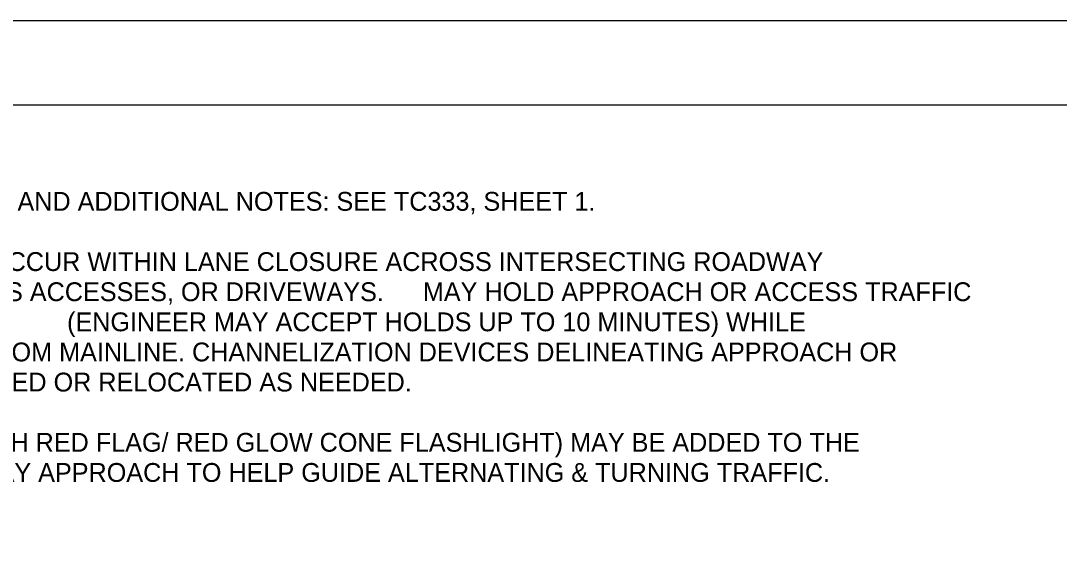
# Model space of a CAD drawing. Extents: x 99999.1 to 100095.7, y 99995 to 100010.7.
# Drawn here: x 100021.34 to 100025.2, y 100008.726 to 100010.687 of the extents above; entities that cross this region are included whole.
import ezdxf

# ---------------------------------------------------------------- set-up
doc = ezdxf.new("R2010")
doc.units = 0
for name, color, linetype in [('SH_GI_GeneralNotesBodyText', 7, 'Continuous'), ('SH_GI_PlotLimits', 7, 'Continuous'), ('SH_GI_SheetBorder', 7, 'Continuous')]:
    doc.layers.add(name, color=color, linetype=linetype)

msp = doc.modelspace()

# ---------------------------------------------------------------- linework, layer by layer
at = {"layer": 'SH_GI_PlotLimits'}
msp.add_lwpolyline([(100019.0625, 99999.6875), (100036.0625, 99999.6875), (100036.0625, 100010.6875), (100019.0625, 100010.6875)], close=True, dxfattribs=at)
at = {"layer": 'SH_GI_SheetBorder'}
msp.add_line((100020, 100010.375), (100035.75, 100010.375), dxfattribs=at)

# ---------------------------------------------------------------- texts
at = {"layer": 'SH_GI_GeneralNotesBodyText'}
for s, p in [('12. FOR LEGEND, TABLES, AND ADDITIONAL NOTES: SEE TC333, SHEET 1.', (100020.1, 100009.981)), ('13. WORK MAY BRIEFLY OCCUR WITHIN LANE CLOSURE ACROSS INTERSECTING ROADWAY ', (100020.1, 100009.757)), ('APPROACHES, BUSINESS ACCESSES, OR DRIVEWAYS. ', (100020.172, 100009.645)), ('MAY HOLD APPROACH OR ACCESS TRAFFIC ', (100022.8346, 100009.645)), (' (ENGINEER MAY ACCEPT HOLDS UP TO 10 MINUTES) WHILE ', (100021.486, 100009.533)), ('RESTRICTING TURNS FROM MAINLINE. CHANNELIZATION DEVICES DELINEATING APPROACH OR ', (100020.172, 100009.421)), ('ACCESS MAY BE REMOVED OR RELOCATED AS NEEDED.', (100020.172, 100009.309)), ('14. SINGLE FLAGGER (WITH RED FLAG/ RED GLOW CONE FLASHLIGHT) MAY BE ADDED TO THE ', (100020.1, 100009.085)), ('INTERSECTING ROADWAY APPROACH TO HELP GUIDE ALTERNATING & TURNING TRAFFIC.', (100020.172, 100008.973))]:
    msp.add_text(s, height=0.07, rotation=360, dxfattribs=at).set_placement(p)

doc.saveas('drawing.dxf')
